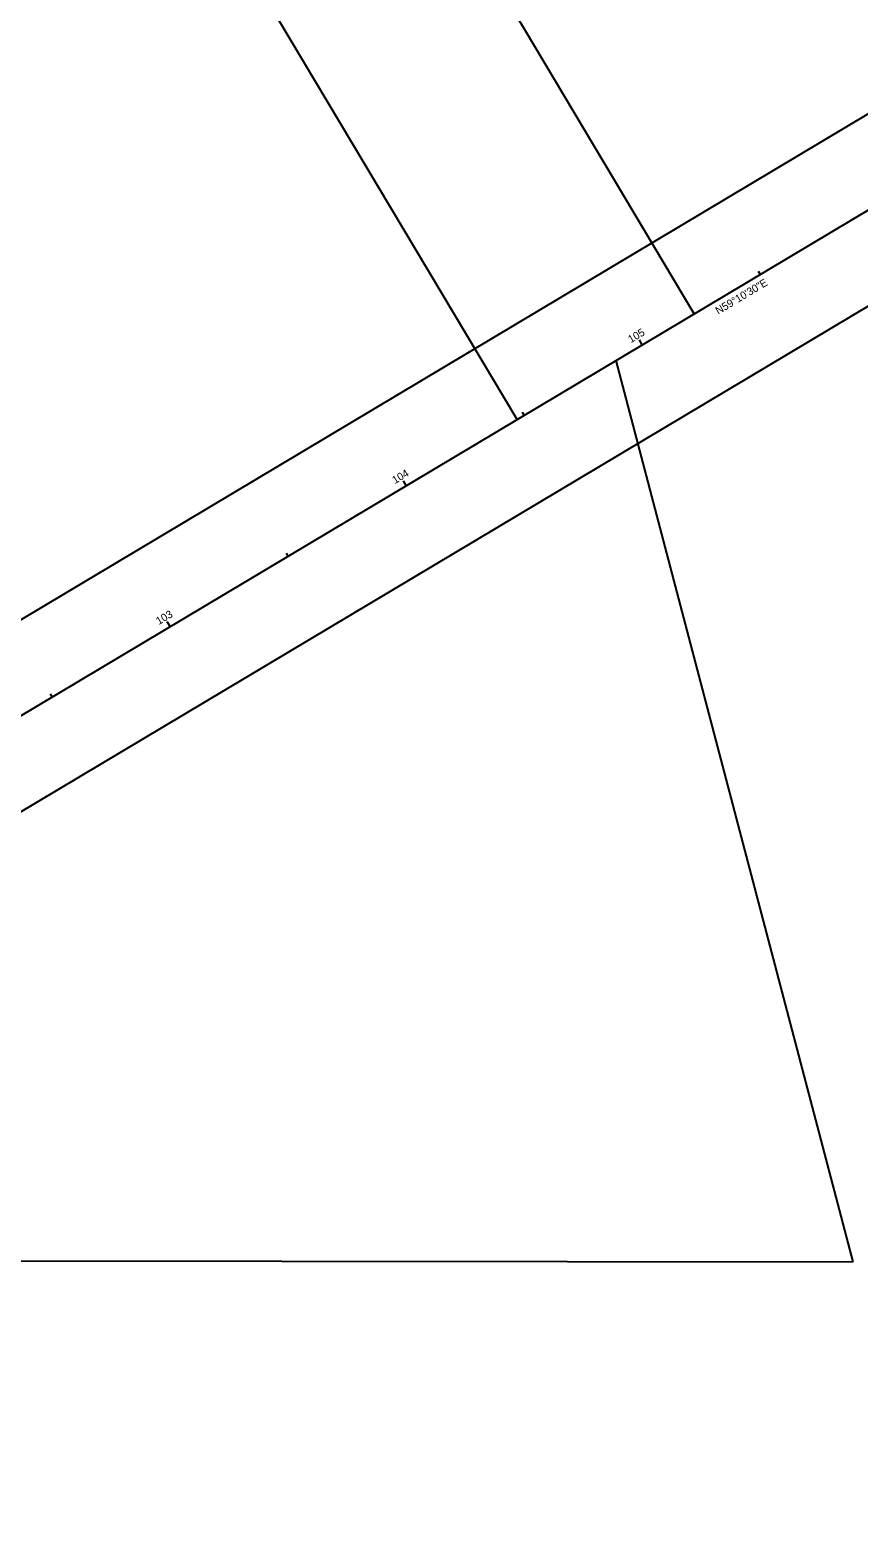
# Model space of a CAD drawing. Extents: x 2351593 to 2354159, y 766293 to 768001.
# Drawn here: x 2352623 to 2352924, y 766753 to 767301 of the extents above; entities that cross this region are included whole.
import ezdxf

# ---------------------------------------------------------------- set-up
doc = ezdxf.new("R2010")
doc.units = 0
for name, color, linetype in [('DV_X_Property_Line', 7, 'Continuous'), ('PTS_ANNO', 7, 'Continuous'), ('RW_X_CL_100_Bearings', 7, 'Continuous'), ('RW_X_CL_500_Bearings', 7, 'Continuous'), ('RW_X_CL_500_Stations', 7, 'Continuous'), ('V-SURV-PARL-LINE', 7, 'Continuous'), ('V-SURV-RWAY-CNTR', 7, 'Continuous')]:
    doc.layers.add(name, color=color, linetype=linetype)

msp = doc.modelspace()

# ---------------------------------------------------------------- linework, layer by layer
at = {"layer": 'DV_X_Property_Line'}
for p, q in [((2352864.14, 767198.39), (2352707.17, 767461.44)), ((2352799.73, 767159.96), (2352632.36, 767440.46)), ((2352921.95, 766853.61), (2352835.7, 767181.42)), ((2352434.4, 766854.25), (2352921.95, 766853.61))]:
    msp.add_line(p, q, dxfattribs=at)
at = {"layer": 'PTS_ANNO'}
for p, q in [((2352428.78, 766973.55), (2354128.21, 767987.61)), ((2352450.22, 766916.47), (2354158.95, 767936.09))]:
    msp.add_line(p, q, dxfattribs=at)
at = {"layer": 'RW_X_CL_500_Stations'}
for p, q in [((2352845.23, 767187.11), (2352844.2, 767188.83)), ((2352759.35, 767135.87), (2352758.74, 767136.9)), ((2352673.48, 767084.63), (2352672.87, 767085.66))]:
    msp.add_line(p, q, dxfattribs=at)
at = {"layer": 'V-SURV-PARL-LINE'}
for p, q in [((2352888.16, 767212.73), (2352887.55, 767213.76)), ((2352845.23, 767187.11), (2352844.2, 767188.83)), ((2352802.29, 767161.49), (2352801.68, 767162.52)), ((2352759.35, 767135.87), (2352758.33, 767137.58)), ((2352716.42, 767110.25), (2352715.8, 767111.28)), ((2352673.48, 767084.63), (2352672.46, 767086.34)), ((2352630.54, 767059), (2352629.93, 767060.03))]:
    msp.add_line(p, q, dxfattribs=at)
at = {"layer": 'V-SURV-RWAY-CNTR'}
msp.add_line((2351616.47, 766453.89), (2354143.58, 767961.85), dxfattribs=at)

# ---------------------------------------------------------------- texts
at = {"layer": 'RW_X_CL_100_Bearings'}
msp.add_text('N59°10\'30"E', height=2.8, rotation=30.825, dxfattribs=at).set_placement((2352872.88, 767198.02))
at = {"layer": 'RW_X_CL_500_Bearings'}
msp.add_text('N59°10\'30"E', height=2.8, rotation=30.825, dxfattribs=at).set_placement((2352872.88, 767198.02))
at = {"layer": 'RW_X_CL_500_Stations'}
msp.add_text('105', height=2.8, rotation=30.825, dxfattribs=at).set_placement((2352841.09, 767187.61))
at = {"layer": 'V-SURV-PARL-LINE'}
for s, p in [('105', (2352841.09, 767187.61)), ('104', (2352755.27, 767136.39)), ('103', (2352669.37, 767085.14))]:
    msp.add_text(s, height=2.8, rotation=30.825, dxfattribs=at).set_placement(p)

doc.saveas('drawing.dxf')
